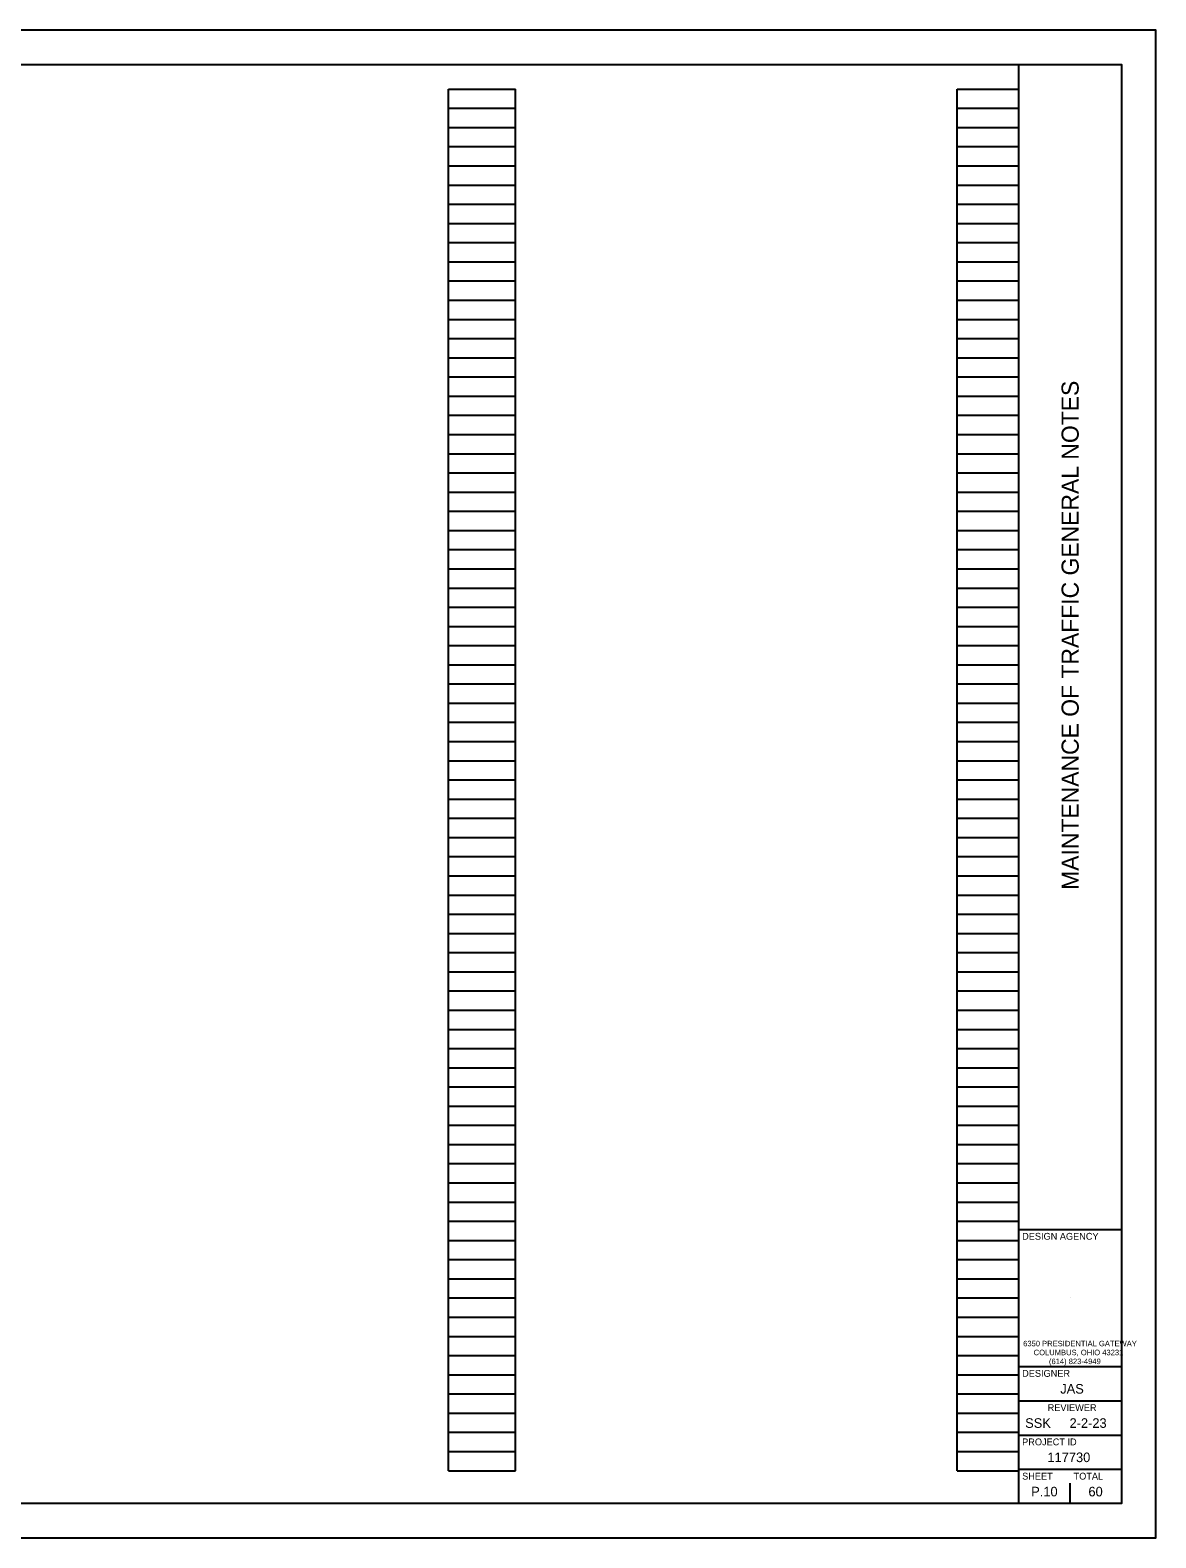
# Model space of a CAD drawing. Extents: x 0 to 34, y 0 to 22.
# Drawn here: x 17.58 to 34, y 0 to 22 of the extents above; entities that cross this region are included whole.
import ezdxf

# ---------------------------------------------------------------- set-up
doc = ezdxf.new("R2010")
doc.units = 0
for name, color, linetype in [('SC_Scratch1', 7, 'Continuous'), ('SH_Border', 7, 'Continuous'), ('SH_Cut_Line', 7, 'Continuous'), ('SH_Data', 7, 'Continuous')]:
    doc.layers.add(name, color=color, linetype=linetype)

msp = doc.modelspace()

# ---------------------------------------------------------------- linework, layer by layer
at = {"layer": 'SC_Scratch1'}
for p, q in [((23.68, 0.98), (23.68, 21.14)), ((23.68, 21.14), (24.66, 21.14)), ((24.66, 0.98), (24.66, 21.14)), ((31.1, 0.98), (31.1, 21.14)), ((31.1, 21.14), (32, 21.14)), ((32, 0.98), (32, 21.14)), ((23.68, 20.86), (24.66, 20.86)), ((31.1, 20.86), (32, 20.86)), ((23.68, 20.58), (24.66, 20.58)), ((31.1, 20.58), (32, 20.58)), ((23.68, 20.3), (24.66, 20.3)), ((31.1, 20.3), (32, 20.3)), ((23.68, 20.02), (24.66, 20.02)), ((31.1, 20.02), (32, 20.02)), ((23.68, 19.74), (24.66, 19.74)), ((31.1, 19.74), (32, 19.74)), ((23.68, 19.46), (24.66, 19.46)), ((31.1, 19.46), (32, 19.46)), ((23.68, 19.18), (24.66, 19.18)), ((31.1, 19.18), (32, 19.18)), ((23.68, 18.9), (24.66, 18.9)), ((31.1, 18.9), (32, 18.9)), ((23.68, 18.62), (24.66, 18.62)), ((31.1, 18.62), (32, 18.62)), ((23.68, 18.34), (24.66, 18.34)), ((31.1, 18.34), (32, 18.34)), ((23.68, 18.06), (24.66, 18.06)), ((31.1, 18.06), (32, 18.06)), ((23.68, 17.78), (24.66, 17.78)), ((31.1, 17.78), (32, 17.78)), ((23.68, 17.5), (24.66, 17.5)), ((31.1, 17.5), (32, 17.5)), ((23.68, 17.22), (24.66, 17.22)), ((31.1, 17.22), (32, 17.22)), ((23.68, 16.94), (24.66, 16.94)), ((31.1, 16.94), (32, 16.94)), ((23.68, 16.66), (24.66, 16.66)), ((31.1, 16.66), (32, 16.66)), ((23.68, 16.38), (24.66, 16.38)), ((31.1, 16.38), (32, 16.38)), ((23.68, 16.1), (24.66, 16.1)), ((31.1, 16.1), (32, 16.1)), ((23.68, 15.82), (24.66, 15.82)), ((31.1, 15.82), (32, 15.82)), ((23.68, 15.54), (24.66, 15.54)), ((31.1, 15.54), (32, 15.54)), ((23.68, 15.26), (24.66, 15.26)), ((31.1, 15.26), (32, 15.26)), ((23.68, 14.98), (24.66, 14.98)), ((31.1, 14.98), (32, 14.98)), ((23.68, 14.7), (24.66, 14.7)), ((31.1, 14.7), (32, 14.7)), ((23.68, 14.42), (24.66, 14.42)), ((31.1, 14.42), (32, 14.42)), ((23.68, 14.14), (24.66, 14.14)), ((31.1, 14.14), (32, 14.14)), ((23.68, 13.86), (24.66, 13.86)), ((31.1, 13.86), (32, 13.86)), ((23.68, 13.58), (24.66, 13.58)), ((31.1, 13.58), (32, 13.58)), ((23.68, 13.3), (24.66, 13.3)), ((31.1, 13.3), (32, 13.3)), ((23.68, 13.02), (24.66, 13.02)), ((31.1, 13.02), (32, 13.02)), ((23.68, 12.74), (24.66, 12.74)), ((31.1, 12.74), (32, 12.74)), ((23.68, 12.46), (24.66, 12.46)), ((31.1, 12.46), (32, 12.46)), ((23.68, 12.18), (24.66, 12.18)), ((31.1, 12.18), (32, 12.18)), ((23.68, 11.9), (24.66, 11.9)), ((31.1, 11.9), (32, 11.9)), ((23.68, 11.62), (24.66, 11.62)), ((31.1, 11.62), (32, 11.62)), ((23.68, 11.34), (24.66, 11.34)), ((31.1, 11.34), (32, 11.34)), ((23.68, 11.06), (24.66, 11.06)), ((31.1, 11.06), (32, 11.06)), ((23.68, 10.78), (24.66, 10.78)), ((31.1, 10.78), (32, 10.78)), ((23.68, 10.5), (24.66, 10.5)), ((31.1, 10.5), (32, 10.5)), ((23.68, 10.22), (24.66, 10.22)), ((31.1, 10.22), (32, 10.22)), ((23.68, 9.94), (24.66, 9.94)), ((31.1, 9.94), (32, 9.94)), ((23.68, 9.66), (24.66, 9.66)), ((31.1, 9.66), (32, 9.66)), ((23.68, 9.38), (24.66, 9.38)), ((31.1, 9.38), (32, 9.38)), ((23.68, 9.1), (24.66, 9.1)), ((31.1, 9.1), (32, 9.1)), ((23.68, 8.82), (24.66, 8.82)), ((31.1, 8.82), (32, 8.82)), ((23.68, 8.54), (24.66, 8.54)), ((31.1, 8.54), (32, 8.54)), ((23.68, 8.26), (24.66, 8.26)), ((31.1, 8.26), (32, 8.26)), ((23.68, 7.98), (24.66, 7.98)), ((31.1, 7.98), (32, 7.98)), ((23.68, 7.7), (24.66, 7.7)), ((31.1, 7.7), (32, 7.7)), ((23.68, 7.42), (24.66, 7.42)), ((31.1, 7.42), (32, 7.42)), ((23.68, 7.14), (24.66, 7.14)), ((31.1, 7.14), (32, 7.14)), ((23.68, 6.86), (24.66, 6.86)), ((31.1, 6.86), (32, 6.86)), ((23.68, 6.58), (24.66, 6.58)), ((31.1, 6.58), (32, 6.58)), ((23.68, 6.3), (24.66, 6.3)), ((31.1, 6.3), (32, 6.3)), ((23.68, 6.02), (24.66, 6.02)), ((31.1, 6.02), (32, 6.02)), ((23.68, 5.74), (24.66, 5.74)), ((31.1, 5.74), (32, 5.74)), ((23.68, 5.46), (24.66, 5.46)), ((31.1, 5.46), (32, 5.46)), ((23.68, 5.18), (24.66, 5.18)), ((31.1, 5.18), (32, 5.18)), ((23.68, 4.9), (24.66, 4.9)), ((31.1, 4.9), (32, 4.9)), ((23.68, 4.62), (24.66, 4.62)), ((31.1, 4.62), (32, 4.62)), ((23.68, 4.34), (24.66, 4.34)), ((31.1, 4.34), (32, 4.34)), ((23.68, 4.06), (24.66, 4.06)), ((31.1, 4.06), (32, 4.06)), ((23.68, 3.78), (24.66, 3.78)), ((31.1, 3.78), (32, 3.78)), ((23.68, 3.5), (24.66, 3.5)), ((31.1, 3.5), (32, 3.5)), ((23.68, 3.22), (24.66, 3.22)), ((31.1, 3.22), (32, 3.22)), ((23.68, 2.94), (24.66, 2.94)), ((31.1, 2.94), (32, 2.94)), ((23.68, 2.66), (24.66, 2.66)), ((31.1, 2.66), (32, 2.66)), ((23.68, 2.38), (24.66, 2.38)), ((31.1, 2.38), (32, 2.38)), ((23.68, 2.1), (24.66, 2.1)), ((31.1, 2.1), (32, 2.1)), ((23.68, 1.82), (24.66, 1.82)), ((31.1, 1.82), (32, 1.82)), ((23.68, 1.54), (24.66, 1.54)), ((31.1, 1.54), (32, 1.54)), ((23.68, 1.26), (24.66, 1.26)), ((31.1, 1.26), (32, 1.26)), ((23.68, 0.98), (24.66, 0.98)), ((31.1, 0.98), (32, 0.98))]:
    msp.add_line(p, q, dxfattribs=at)
at = {"layer": 'SH_Border'}
for p, q in [((32, 0.5), (32, 21.5)), ((32, 4.5), (33.5, 4.5)), ((32, 2.5), (33.5, 2.5)), ((32, 2), (33.5, 2)), ((32, 1.5), (33.5, 1.5)), ((32, 1), (33.5, 1))]:
    msp.add_line(p, q, dxfattribs=at)
msp.add_lwpolyline([(1.5, 21.5), (33.5, 21.5), (33.5, 0.5), (1.5, 0.5)], close=True, dxfattribs=at)
at = {"layer": 'SH_Cut_Line'}
msp.add_lwpolyline([(0, 0), (34, 0), (34, 22), (0, 22)], close=True, dxfattribs=at)
at = {"layer": 'SH_Data'}
for p, q in [((32.75, 3.5), (32.75, 3.5)), ((32.375, 0.675), (32.375, 0.675)), ((32.75, 0.5), (32.75, 0.8))]:
    msp.add_line(p, q, dxfattribs=at)

# ---------------------------------------------------------------- texts
msp.add_text('MAINTENANCE OF TRAFFIC GENERAL NOTES', height=0.25, rotation=90, dxfattribs=at).set_placement((32.875, 9.455))
for s, height, p in [('DESIGN AGENCY', 0.1, (32.05, 4.35)), ('6350 PRESIDENTIAL GATEWAY', 0.08, (32.065, 2.795)), ('6350 PRESIDENTIAL GATEWAY', 0.08, (32.065, 2.795)), ('COLUMBUS, OHIO 43231', 0.08, (32.218, 2.665)), ('COLUMBUS, OHIO 43231', 0.08, (32.218, 2.665)), ('DESIGNER', 0.1, (32.05, 2.35)), ('(614) 823-4949', 0.08, (32.441, 2.535)), ('(614) 823-4949', 0.08, (32.441, 2.535)), ('JAS', 0.14, (32.606, 2.105)), ('REVIEWER', 0.1, (32.422, 1.85)), ('SSK', 0.14, (32.094, 1.605)), ('2-2-23', 0.14, (32.741, 1.605)), ('PROJECT ID', 0.1, (32.05, 1.35)), ('117730', 0.14, (32.419, 1.105)), ('SHEET', 0.1, (32.05, 0.85)), ('TOTAL', 0.1, (32.8, 0.85)), ('P.10', 0.14, (32.182, 0.605)), ('60', 0.14, (33.017, 0.605))]:
    msp.add_text(s, height=height, dxfattribs=at).set_placement(p)

doc.saveas('drawing.dxf')
